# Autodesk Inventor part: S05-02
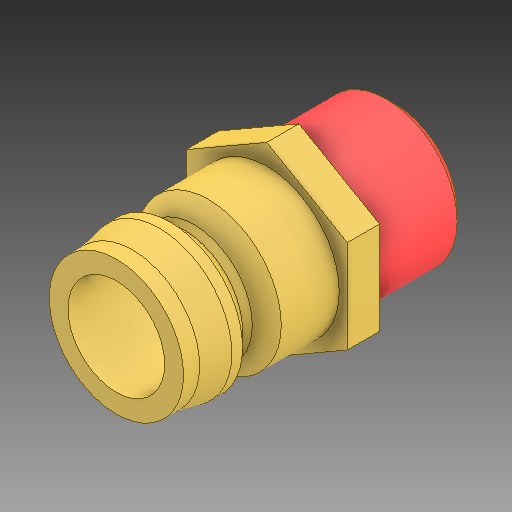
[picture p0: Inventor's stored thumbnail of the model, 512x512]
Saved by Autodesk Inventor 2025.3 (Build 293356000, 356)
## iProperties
Created: 2025-04
Part Number: S05-02
Material: Všeobecné
Document SubType Name: Modeling
Designer: Patrik
Density: 1 g/cm^3
Appearance: Výchozí
Description: Přípojka s těsnícím prostředkem
Stock Number: E 2000 D/13/1/4
Mass: 1.96918 g
Surface Area: 20.9425 cm^2
Volume: 1.96918 cm^3
User Status: 2.0401
Author: Patrik
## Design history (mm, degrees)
feature "Base1"
node "Těleso1"
